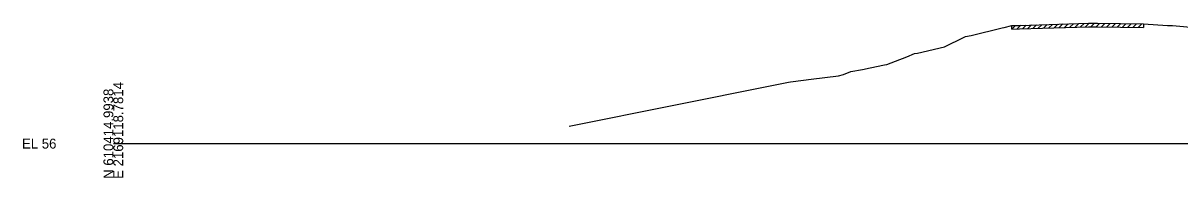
# Model space of a CAD drawing. Extents: x -26 to 6803, y -10 to 19606.
# Drawn here: x 1974.3 to 2303.8, y 10990.3 to 11034.2 of the extents above; entities that cross this region are included whole.
import ezdxf

# ---------------------------------------------------------------- set-up
doc = ezdxf.new("R2010")
doc.units = 0
for name, color, linetype in [('RD_GPK_XS_Cell', 7, 'Continuous'), ('RD_XS_ExGround', 7, 'Continuous'), ('RD_XS_ExPaveRet', 7, 'Continuous')]:
    doc.layers.add(name, color=color, linetype=linetype)

msp = doc.modelspace()

# ---------------------------------------------------------------- linework, layer by layer
at = {"layer": 'RD_GPK_XS_Cell'}
msp.add_line((2000, 11000), (2400, 11000), dxfattribs=at)
at = {"layer": 'RD_XS_ExGround'}
msp.add_lwpolyline([(2129.81, 11004.98), (2160.15, 11010.99), (2187.13, 11016.41), (2192.32, 11017.47), (2192.86, 11017.52), (2193.62, 11017.64), (2198.74, 11018.29), (2206.56, 11019.27), (2207.98, 11019.58), (2210.02, 11020.52), (2213.43, 11021.05), (2215.55, 11021.5), (2219.63, 11022.34), (2220.29, 11022.48), (2222.83, 11023.37), (2226.01, 11024.63), (2228.18, 11025.56), (2229.09, 11025.71), (2236.76, 11027.5), (2242.32, 11030.19), (2242.77, 11030.4), (2244.31, 11030.74), (2253.19, 11032.88), (2253.71, 11032.98), (2255.95, 11033.5), (2258.06, 11033.57), (2277.76, 11034.18), (2280.37, 11034.15), (2293.46, 11033.98), (2300.3, 11033.57), (2301.64, 11033.5), (2308.86, 11032.9)], dxfattribs=at)
at = {"layer": 'RD_XS_ExPaveRet'}
for p, q in [((2255.95, 11032.5), (2256.99, 11033.54)), ((2255.95, 11032.5), (2255.95, 11033.5)), ((2255.95, 11032.5), (2258.06, 11032.57)), ((2257.45, 11032.55), (2258.49, 11033.59)), ((2258.06, 11032.57), (2277.76, 11033.18)), ((2258.95, 11032.6), (2259.99, 11033.63)), ((2260.45, 11032.65), (2261.49, 11033.68)), ((2261.95, 11032.69), (2262.99, 11033.73)), ((2263.45, 11032.74), (2264.49, 11033.77)), ((2264.95, 11032.79), (2265.99, 11033.82)), ((2266.45, 11032.83), (2267.49, 11033.86)), ((2267.95, 11032.88), (2268.99, 11033.91)), ((2269.45, 11032.93), (2270.49, 11033.96)), ((2270.95, 11032.97), (2271.99, 11034)), ((2272.45, 11033.02), (2273.49, 11034.05)), ((2273.95, 11033.07), (2274.99, 11034.1)), ((2275.45, 11033.11), (2276.49, 11034.14)), ((2276.95, 11033.16), (2277.98, 11034.18)), ((2277.76, 11033.18), (2280.37, 11033.15)), ((2278.45, 11033.17), (2279.44, 11034.16)), ((2279.95, 11033.15), (2280.94, 11034.14)), ((2280.37, 11033.15), (2293.46, 11032.98)), ((2281.45, 11033.13), (2282.44, 11034.12)), ((2282.95, 11033.11), (2283.94, 11034.1)), ((2284.45, 11033.09), (2285.44, 11034.08)), ((2285.95, 11033.07), (2286.94, 11034.06)), ((2287.45, 11033.05), (2288.44, 11034.04)), ((2288.95, 11033.03), (2289.94, 11034.02)), ((2290.45, 11033.02), (2291.44, 11034)), ((2291.95, 11033), (2292.94, 11033.98)), ((2293.46, 11033.98), (2293.46, 11032.98)), ((2293.46, 11032.98), (2293.46, 11032.98))]:
    msp.add_line(p, q, dxfattribs=at)

# ---------------------------------------------------------------- texts
at = {"layer": 'RD_GPK_XS_Cell'}
for s, p in [('N 610414.9938', (2000, 10990)), ('E 2169118.7814', (2002.8, 10990))]:
    msp.add_text(s, height=2.8, rotation=90, dxfattribs=at).set_placement(p)
msp.add_text('EL 56', height=2.8, dxfattribs=at).set_placement((1974, 10998.6))

doc.saveas('drawing.dxf')
